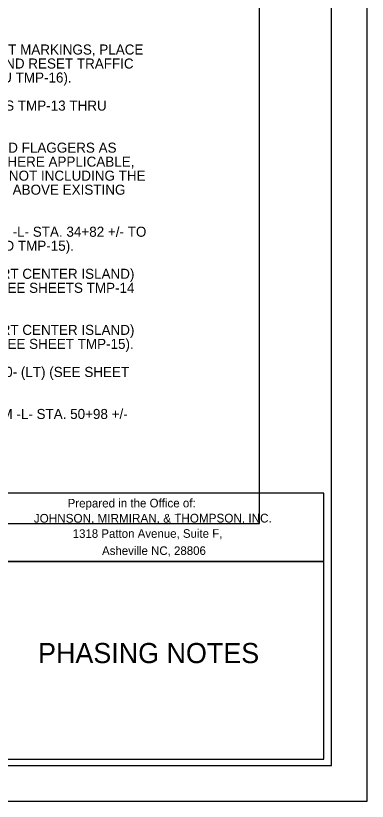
# Model space of a CAD drawing. Extents: x 764226 to 769781, y 650021 to 652521.
# Drawn here: x 767893 to 768137, y 651421 to 651968 of the extents above; entities that cross this region are included whole.
import ezdxf

# ---------------------------------------------------------------- set-up
doc = ezdxf.new("R2010")
doc.units = 0
for name, color, linetype in [('Default', 7, 'Continuous'), ('DEV BORDER CELL', 7, 'Continuous'), ('Scratch_Level_0', 7, 'Continuous'), ('Sheet Plan CELL', 7, 'Continuous'), ('Sheet Plot Border Outside CELL', 7, 'Continuous'), ('Sheet Title CELL', 7, 'Continuous')]:
    doc.layers.add(name, color=color, linetype=linetype)

msp = doc.modelspace()

# ---------------------------------------------------------------- linework, layer by layer
at = {"layer": 'DEV BORDER CELL'}
for points in [[(768112.34, 652496.28), (766612.34, 652496.28), (766612.34, 651446.28), (768112.34, 651446.28)], [(768107.19, 651588.05), (767871.19, 651588.05), (767871.19, 651450.55), (768107.19, 651450.55)]]:
    msp.add_lwpolyline(points, close=True, dxfattribs=at)
at = {"layer": 'Scratch_Level_0'}
msp.add_lwpolyline([(768062.34, 652446.28), (766662.34, 652446.28), (766662.34, 651496.28), (767541.19, 651496.28), (767541.19, 651614.55), (768062.34, 651614.55)], close=True, dxfattribs=at)
at = {"layer": 'Sheet Plan CELL'}
msp.add_lwpolyline([(768107.19, 651635.57), (767815.52, 651635.57), (767815.52, 651588.05), (768107.19, 651588.05)], close=True, dxfattribs=at)
at = {"layer": 'Sheet Plot Border Outside CELL'}
msp.add_lwpolyline([(766449.34, 651421.28), (768137.34, 651421.28), (768137.34, 652521.28), (766449.34, 652521.28)], close=True, dxfattribs=at)

# ---------------------------------------------------------------- texts
at = {"layer": 'Default'}
for s, p in [('REMOVE, AS NECESSARY, EXISTING PAVEMENT MARKINGS, PLACE ', (767671.45, 651940.89)), ('TEMPORARY PAVEMENT MARKINGS (PAINT), AND RESET TRAFFIC ', (767671.45, 651931.14)), ('CONTROL DEVICES (SEE SHEETS TMP-13 THRU TMP-16).', (767671.45, 651921.38)), ('SHIFT TRAFFIC TO NEW PATTERN (SEE SHEETS TMP-13 THRU ', (767671.45, 651901.88)), ('USING RSD 1101.02, SHEETS 1 AND 2 OF 19, AND FLAGGERS AS ', (767671.45, 651872.61)), ('NECESSARY, REMOVE EXISTING PAVEMENT WHERE APPLICABLE, ', (767671.45, 651862.86)), ('AND CONSTRUCT THE FOLLOWING UP TO BUT NOT INCLUDING THE ', (767671.45, 651853.11)), ('FINAL LAYER OF SURFACE COURSE, WEDGING ABOVE EXISTING ', (767671.45, 651843.35)), ('PROPOSED ROADWAY, AND SIDEWALKS FROM -L- STA. 34+82 +/- TO ', (767671.45, 651814.09)), ('-L- STA. 49+82 +/- (LT) (SEE SHEETS TMP-14 AND TMP-15).', (767671.45, 651804.34)), ('PROPOSED SPLITTER ISLAND AND CURBING (RT CENTER ISLAND) ', (767671.45, 651784.83)), ('FROM -L- STA. 35+44 +/- TO -L- STA. 43+88 +/- (SEE SHEETS TMP-14 ', (767671.45, 651775.07)), ('PROPOSED SPLITTER ISLAND AND CURBING (RT CENTER ISLAND) ', (767671.45, 651745.81)), ('FROM -L- STA. 46+56 +/- TO -L- STA. 49+70 +/- (SEE SHEET TMP-15).', (767671.45, 651736.06)), ('PROPOSED ROADWAY, AND SIDEWALK ON -Y10- (LT) (SEE SHEET ', (767671.45, 651716.55)), ('PROPOSED ROADWAY, AND SIDEWALKS, FROM -L- STA. 50+98 +/- ', (767671.45, 651687.29))]:
    msp.add_text(s, height=7, rotation=359.9999, dxfattribs=at).set_placement(p)
msp.add_text('PHASING NOTES', height=14, dxfattribs=at).set_placement((767908.11, 651517.43))
at = {"layer": 'Sheet Title CELL'}
for s, height, p in [('Prepared in the Office of:', 5.9987, (767928.69, 651625.72)), ('JOHNSON, MIRMIRAN, & THOMPSON, INC.', 6.0929, (767905.17, 651615.12)), ('1318 Patton Avenue, Suite F,', 5.9679, (767932.21, 651604.57)), ('Asheville NC, 28806', 5.9679, (767952.66, 651592.65))]:
    msp.add_text(s, height=height, rotation=0.0516, dxfattribs=at).set_placement(p)

doc.saveas('drawing.dxf')
